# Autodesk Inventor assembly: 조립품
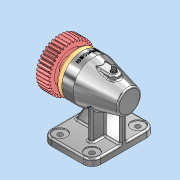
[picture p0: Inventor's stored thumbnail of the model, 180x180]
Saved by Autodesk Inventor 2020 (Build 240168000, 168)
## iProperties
Created: 2024-12
Part Number: 조립품
Document SubType Name: Assembly
Designer: 1강의실14
Author: 1강의실14
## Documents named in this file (15)
- C:\Users\1강의실14\Desktop\741204V1003\조립품.iam
- C:\Users\1강의실14\Desktop\741204V1003\본체.ipt
- C:\Users\1강의실14\Desktop\741204V1003\축.ipt
- C:\Users\1강의실14\Desktop\741204V1003\앵귤러 볼 베어링 7003A.ipt
- C:\Users\1강의실14\Desktop\741204V1003\앵귤러 볼 제어링 7204A.ipt
- C:\Users\1강의실14\Desktop\741204V1003\커버.ipt
- C:\Users\1강의실14\Desktop\741204V1003\오일 실 20 32 8.ipt
- C:\Users\1강의실14\Desktop\741204V1003\육각 소켓 머리 볼트 M4x10.ipt
- C:\Users\1강의실14\Desktop\741204V1003\평행 키 4x4x14.ipt
- C:\Users\1강의실14\Desktop\741204V1003\스퍼기어스퍼기어.ipt
- C:\Users\1강의실14\Desktop\741204V1003\스프링 와셔 M8.ipt
- C:\Users\1강의실14\Desktop\741204V1003\육각 너트 M8.ipt
- C:\Users\1강의실14\Desktop\741204V1003\실링.ipt
- C:\Users\1강의실14\Desktop\741204V1003\그리스 니플 M6x0.75.ipt
- C:\Users\1강의실14\Desktop\741204V1003\평와셔 M8.ipt
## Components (1 placed, 1 different names)
1. 그리스 니플 M6x0.75:1
